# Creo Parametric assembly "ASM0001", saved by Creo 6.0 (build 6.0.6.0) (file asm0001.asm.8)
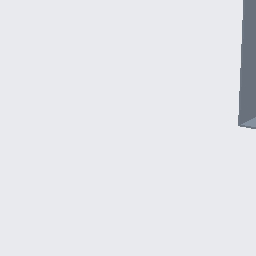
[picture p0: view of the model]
Units: Inch lbm Second (Pro/E Default); INCH, POUND, SECS

Created from: INLBS_ASM_DESIGN.ASM

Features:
  1. datum plane "ASM_RIGHT"
  2. datum plane "ASM_TOP"
  3. datum plane "ASM_FRONT"
  4. coordinate system
  5. component "PRT0001"
  6. component "LEFT"
  7. coordinate system
  8. component "BACK"
  9. component "PRT0002"
  10. component "RIGHT"

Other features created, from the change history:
  component "BACK.PRT"
  component "RIGHT.PRT"
  component "PRT0002.PRT"

Other named items: ACS4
